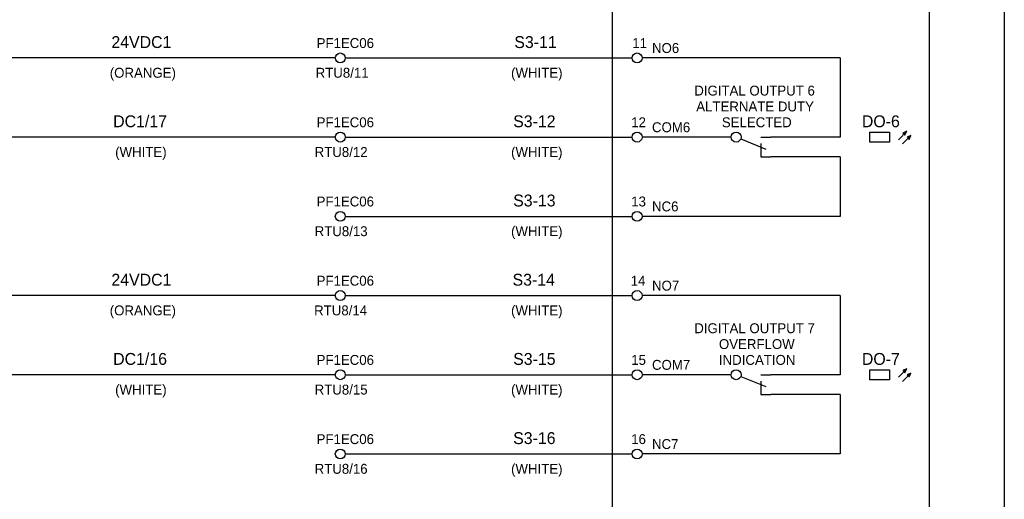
# Model space of a CAD drawing. Extents: x 0 to 841, y 0 to 594.
# Drawn here: x 580.3 to 829, y 168.6 to 289.7 of the extents above; entities that cross this region are included whole.
import ezdxf

# ---------------------------------------------------------------- set-up
doc = ezdxf.new("R2010")
doc.units = 0
for name, color, linetype in [('A1BORDER', 7, 'Continuous'), ('Level 1', 7, 'Continuous'), ('Level 10', 7, 'Continuous')]:
    doc.layers.add(name, color=color, linetype=linetype)

msp = doc.modelspace()

# ---------------------------------------------------------------- linework, layer by layer
at = {"layer": 'A1BORDER'}
msp.add_line((829, 581), (829, 15), dxfattribs=at)
at = {"layer": 'Level 1'}
for p, q in [((660, 280), (360, 280)), ((662.5, 280), (735, 280)), ((787.5, 280), (737.5, 280)), ((787.5, 280), (787.5, 260)), ((660, 260), (360, 260)), ((662.5, 260), (735, 260)), ((760, 260), (737.5, 260)), ((787.5, 260), (770, 260)), ((787.5, 255), (770, 255)), ((787.5, 255), (787.5, 240)), ((662.5, 240), (735, 240)), ((787.5, 240), (737.5, 240)), ((660, 220), (360, 220)), ((662.5, 220), (735, 220)), ((787.5, 220), (737.5, 220)), ((787.5, 220), (787.5, 200)), ((660, 200), (360, 200)), ((662.5, 200), (735, 200)), ((760, 200), (737.5, 200)), ((787.5, 200), (770, 200)), ((787.5, 195), (770, 195)), ((787.5, 195), (787.5, 180)), ((662.5, 180), (735, 180)), ((787.5, 180), (737.5, 180))]:
    msp.add_line(p, q, dxfattribs=at)
for points in [[(730, 540), (810, 540), (810, 80), (730, 80)], [(795, 261.25), (800, 261.25), (800, 258.75), (795, 258.75)], [(795, 201.25), (800, 201.25), (800, 198.75), (795, 198.75)]]:
    msp.add_lwpolyline(points, close=True, dxfattribs=at)
for centre in [(661.25, 280), (736.25, 280), (661.25, 260), (736.25, 260), (661.25, 240), (736.25, 240), (661.25, 220), (736.25, 220), (661.25, 200), (736.25, 200), (661.25, 180), (736.25, 180)]:
    msp.add_circle(centre, 1.25, dxfattribs=at)
at = {"layer": 'Level 10'}
for p, q in [((802.23, 259.36), (804.36, 261.48)), ((803.79, 261.23), (804.24, 261.23)), ((804.12, 261.38), (804.31, 261.38)), ((762.41, 259.54), (768.75, 257)), ((767.5, 260), (770, 260)), ((803.29, 258.3), (805.41, 260.42)), ((803.46, 261.07), (804.17, 261.07)), ((803.5, 260.93), (804.11, 260.93)), ((803.64, 260.77), (804.03, 260.77)), ((803.8, 260.62), (803.97, 260.62)), ((804.52, 260.01), (805.23, 260.01)), ((804.56, 259.87), (805.16, 259.87)), ((804.71, 259.72), (805.1, 259.72)), ((804.85, 260.17), (805.3, 260.17)), ((804.86, 259.56), (805.03, 259.56)), ((805.18, 260.31), (805.37, 260.31)), ((767.5, 258.37), (767.5, 255)), ((767.5, 255), (770, 255)), ((802.23, 199.36), (804.36, 201.48)), ((762.41, 199.54), (768.75, 197)), ((767.5, 200), (770, 200)), ((803.29, 198.3), (805.41, 200.42)), ((803.46, 201.08), (804.17, 201.08)), ((803.5, 200.93), (804.11, 200.93)), ((803.64, 200.78), (804.03, 200.78)), ((803.79, 201.22), (804.24, 201.22)), ((803.8, 200.62), (803.97, 200.62)), ((804.12, 201.38), (804.31, 201.38)), ((804.52, 200.02), (805.23, 200.02)), ((804.56, 199.87), (805.16, 199.87)), ((804.71, 199.72), (805.1, 199.72)), ((804.85, 200.16), (805.3, 200.16)), ((804.86, 199.56), (805.03, 199.56)), ((805.18, 200.31), (805.37, 200.31)), ((767.5, 198.37), (767.5, 195)), ((767.5, 195), (770, 195))]:
    msp.add_line(p, q, dxfattribs=at)
for points in [[(804.36, 261.48), (803.38, 261.04), (803.91, 260.5)], [(805.41, 260.42), (804.44, 259.98), (804.98, 259.44)], [(804.36, 201.48), (803.38, 201.04), (803.91, 200.5)], [(805.41, 200.42), (804.44, 199.98), (804.98, 199.44)]]:
    msp.add_lwpolyline(points, close=True, dxfattribs=at)
for centre in [(761.25, 260), (761.25, 200)]:
    msp.add_circle(centre, 1.25, dxfattribs=at)

# ---------------------------------------------------------------- texts
at = {"layer": 'Level 1'}
for s, height, p in [('24VDC1', 3, (603.43, 282.5)), ('PF1EC06', 2.5, (655.28, 282.5)), ('S3-11', 3, (705.22, 282.5)), ('11', 2.5, (735.01, 282.5)), ('NO6', 2.5, (740, 281.25)), ('(ORANGE)', 2.5, (603.02, 275)), ('RTU8/11', 2.5, (655.03, 275)), ('(WHITE)', 2.5, (704.4, 275)), ('DIGITAL OUTPUT 6', 2.5, (750.68, 270.5)), ('ALTERNATE DUTY', 2.5, (751.18, 266.5)), ('DC1/17', 3, (603.88, 262.5)), ('PF1EC06', 2.5, (655.28, 262.5)), ('S3-12', 3, (704.93, 262.5)), ('12', 2.5, (734.75, 262.5)), ('COM6', 2.5, (740, 261.25)), ('SELECTED', 2.5, (757.65, 262.5)), ('DO-6', 3, (793.02, 262.5)), ('(WHITE)', 2.5, (604.39, 255)), ('RTU8/12', 2.5, (654.78, 255)), ('(WHITE)', 2.5, (704.4, 255)), ('PF1EC06', 2.5, (655.28, 242.5)), ('S3-13', 3, (704.93, 242.5)), ('13', 2.5, (734.75, 242.5)), ('NC6', 2.5, (740, 241.25)), ('RTU8/13', 2.5, (654.78, 235)), ('(WHITE)', 2.5, (704.4, 235)), ('24VDC1', 3, (603.43, 222.5)), ('PF1EC06', 2.5, (655.28, 222.5)), ('S3-14', 3, (704.77, 222.5)), ('14', 2.5, (734.63, 222.5)), ('NO7', 2.5, (740, 221.25)), ('(ORANGE)', 2.5, (603.02, 215)), ('RTU8/14', 2.5, (654.65, 215)), ('(WHITE)', 2.5, (704.4, 215)), ('DIGITAL OUTPUT 7', 2.5, (750.68, 210.5)), ('OVERFLOW', 2.5, (756.91, 206.5)), ('DC1/16', 3, (603.88, 202.5)), ('PF1EC06', 2.5, (655.28, 202.5)), ('S3-15', 3, (704.93, 202.5)), ('15', 2.5, (734.75, 202.5)), ('INDICATION', 2.5, (756.91, 202.5)), ('DO-7', 3, (793.02, 202.5)), ('COM7', 2.5, (740, 201.25)), ('(WHITE)', 2.5, (604.39, 195)), ('RTU8/15', 2.5, (654.78, 195)), ('(WHITE)', 2.5, (704.4, 195)), ('PF1EC06', 2.5, (655.28, 182.5)), ('S3-16', 3, (704.93, 182.5)), ('16', 2.5, (734.75, 182.5)), ('NC7', 2.5, (740, 181.25)), ('RTU8/16', 2.5, (654.78, 175)), ('(WHITE)', 2.5, (704.4, 175))]:
    msp.add_text(s, height=height, dxfattribs=at).set_placement(p)

doc.saveas('drawing.dxf')
